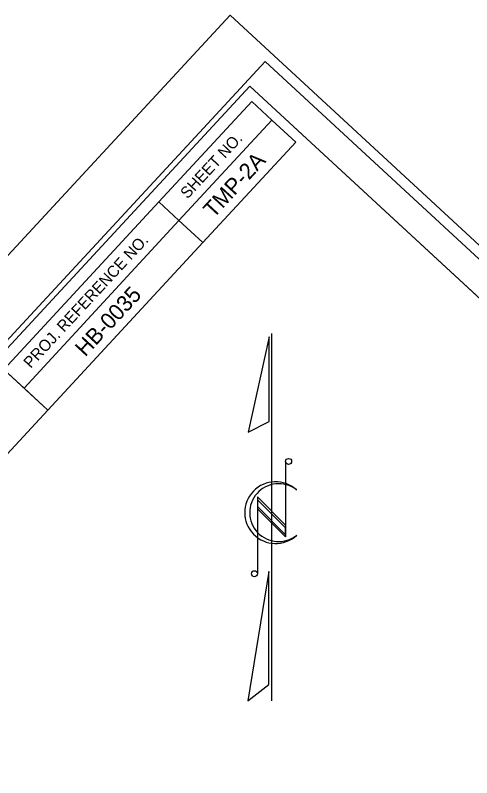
# Model space of a CAD drawing. Extents: x 1767460 to 1770129, y 996106 to 1001438.
# Drawn here: x 1769038.8 to 1769280.5, y 1001034.4 to 1001438.5 of the extents above; entities that cross this region are included whole.
import ezdxf

# ---------------------------------------------------------------- set-up
doc = ezdxf.new("R2010")
doc.units = 0
for name, color, linetype in [('E_NCDOT_Terrain_Model_Contour_Minor', 7, 'Continuous'), ('E_NCDOT_Terrain_Model_Points_Low', 7, 'Continuous'), ('E_NCDOT_Terrain_Model_Triangle_Vertices', 7, 'Continuous'), ('P_NCDOT_Terrain_Breakline', 7, 'Continuous'), ('P_NCDOT_Terrain_Points_High', 7, 'Continuous'), ('P_RDY_Edge_of_Travel', 7, 'Continuous'), ('P_RDY_TL_Edge_of_Travel_Sub', 7, 'Continuous')]:
    doc.layers.add(name, color=color, linetype=linetype)

msp = doc.modelspace()

# ---------------------------------------------------------------- linework, layer by layer
at = {"layer": 'E_NCDOT_Terrain_Model_Contour_Minor'}
msp.add_lwpolyline([(1768744.05, 999038.07), (1770128.77, 1000536.12), (1769152.55, 1001438.49), (1767767.83, 999940.44)], close=True, dxfattribs=at)
at = {"layer": 'E_NCDOT_Terrain_Model_Points_Low'}
msp.add_lwpolyline([(1767804.38, 999935.46), (1769171.05, 1001413.98), (1770107.33, 1000548.53), (1768740.66, 999070.01)], close=True, dxfattribs=at)
at = {"layer": 'E_NCDOT_Terrain_Model_Triangle_Vertices'}
msp.add_lwpolyline([(1769163.02, 1001400.87), (1767932.52, 1000069.67), (1768864.37, 999208.32), (1770094.87, 1000539.52)], close=True, dxfattribs=at)
at = {"layer": 'P_NCDOT_Terrain_Breakline'}
for p, q in [((1769174.56, 1001075.12), (1769174.56, 1001269.83)), ((1769181.9, 1001202.07), (1769181.9, 1001162.11)), ((1769187.41, 1001187.18), (1769187.62, 1001187.03)), ((1769181.9, 1001168.34), (1769167.01, 1001183.23)), ((1769167.01, 1001183.23), (1769167.01, 1001142.61)), ((1769181.9, 1001166.87), (1769167.01, 1001181.76)), ((1769167.01, 1001181.76), (1769167.01, 1001178.1)), ((1769181.9, 1001163.22), (1769167.01, 1001178.1)), ((1769167.01, 1001178.1), (1769181.9, 1001163.22)), ((1769181.9, 1001162.11), (1769167.01, 1001177)), ((1769181.9, 1001163.22), (1769181.9, 1001166.87))]:
    msp.add_line(p, q, dxfattribs=at)
for points in [[(1769173.21, 1001268.12), (1769162.1, 1001217.56), (1769173.21, 1001223.19)], [(1769172.97, 1001143.72), (1769161.95, 1001075.12), (1769172.97, 1001083.8)]]:
    msp.add_lwpolyline(points, close=True, dxfattribs=at)
for centre in [(1769183.49, 1001202.04), (1769165.42, 1001142.55)]:
    msp.add_circle(centre, 1.59, dxfattribs=at)
for centre, radius, start, end in [((1769176.63, 1001174.91), 16.36, 47.84, 312.3941), ((1769178.21, 1001174.92), 15.33, 53.095, 308.6287)]:
    msp.add_arc(centre, radius, start, end, dxfattribs=at)
at = {"layer": 'P_NCDOT_Terrain_Points_High'}
msp.add_lwpolyline([(1769163.02, 1001400.87), (1767932.52, 1000069.67), (1768864.37, 999208.32), (1769639.43, 1000046.81), (1769513.61, 1000163.11), (1769964.83, 1000651.25), (1769968.19, 1000656.62)], close=True, dxfattribs=at)
at = {"layer": 'P_RDY_Edge_of_Travel'}
msp.add_lwpolyline([(1768868.65, 1001073.25), (1769032.76, 1001250.8), (1769056.07, 1001229.26), (1768891.95, 1001051.71)], close=True, dxfattribs=at)
at = {"layer": 'P_RDY_TL_Edge_of_Travel_Sub'}
for points in [[(1769125.45, 1001329.7), (1769174.67, 1001382.95), (1769164.02, 1001392.79), (1769114.8, 1001339.55)], [(1769125.45, 1001329.7), (1769174.67, 1001382.95), (1769187.32, 1001371.25), (1769138.1, 1001318.01)], [(1769032.76, 1001250.8), (1769114.8, 1001339.55), (1769125.45, 1001329.7), (1769043.41, 1001240.95)], [(1769125.45, 1001329.7), (1769043.41, 1001240.95), (1769056.07, 1001229.26), (1769138.1, 1001318.01)]]:
    msp.add_lwpolyline(points, close=True, dxfattribs=at)

# ---------------------------------------------------------------- texts
for s, height, rotation, p in [('SHEET NO.', 6.043, 47.2518, (1769129.99, 1001340.85)), ('TMP-2A', 8.46, 47.2512, (1769143.75, 1001330.57)), ('PROJ. REFERENCE NO.', 6.0427, 47.2518, (1769046.95, 1001251.01)), ('HB-0035', 8.46, 47.2512, (1769075.83, 1001257.1))]:
    msp.add_text(s, height=height, rotation=rotation, dxfattribs=at).set_placement(p)

doc.saveas('drawing.dxf')
